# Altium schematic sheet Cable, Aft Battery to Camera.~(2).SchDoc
size Tabloid; Organization: Monterey Bay Aquarium Research Institute; Address1: 7700 Sandholdt Rd; Address2: Moss Landing, CA 95039-9644; Author: Hans Thomas; CompanyName: MBARI; DrawnBy: Hans Thomas; Engineer: Hans Thomas
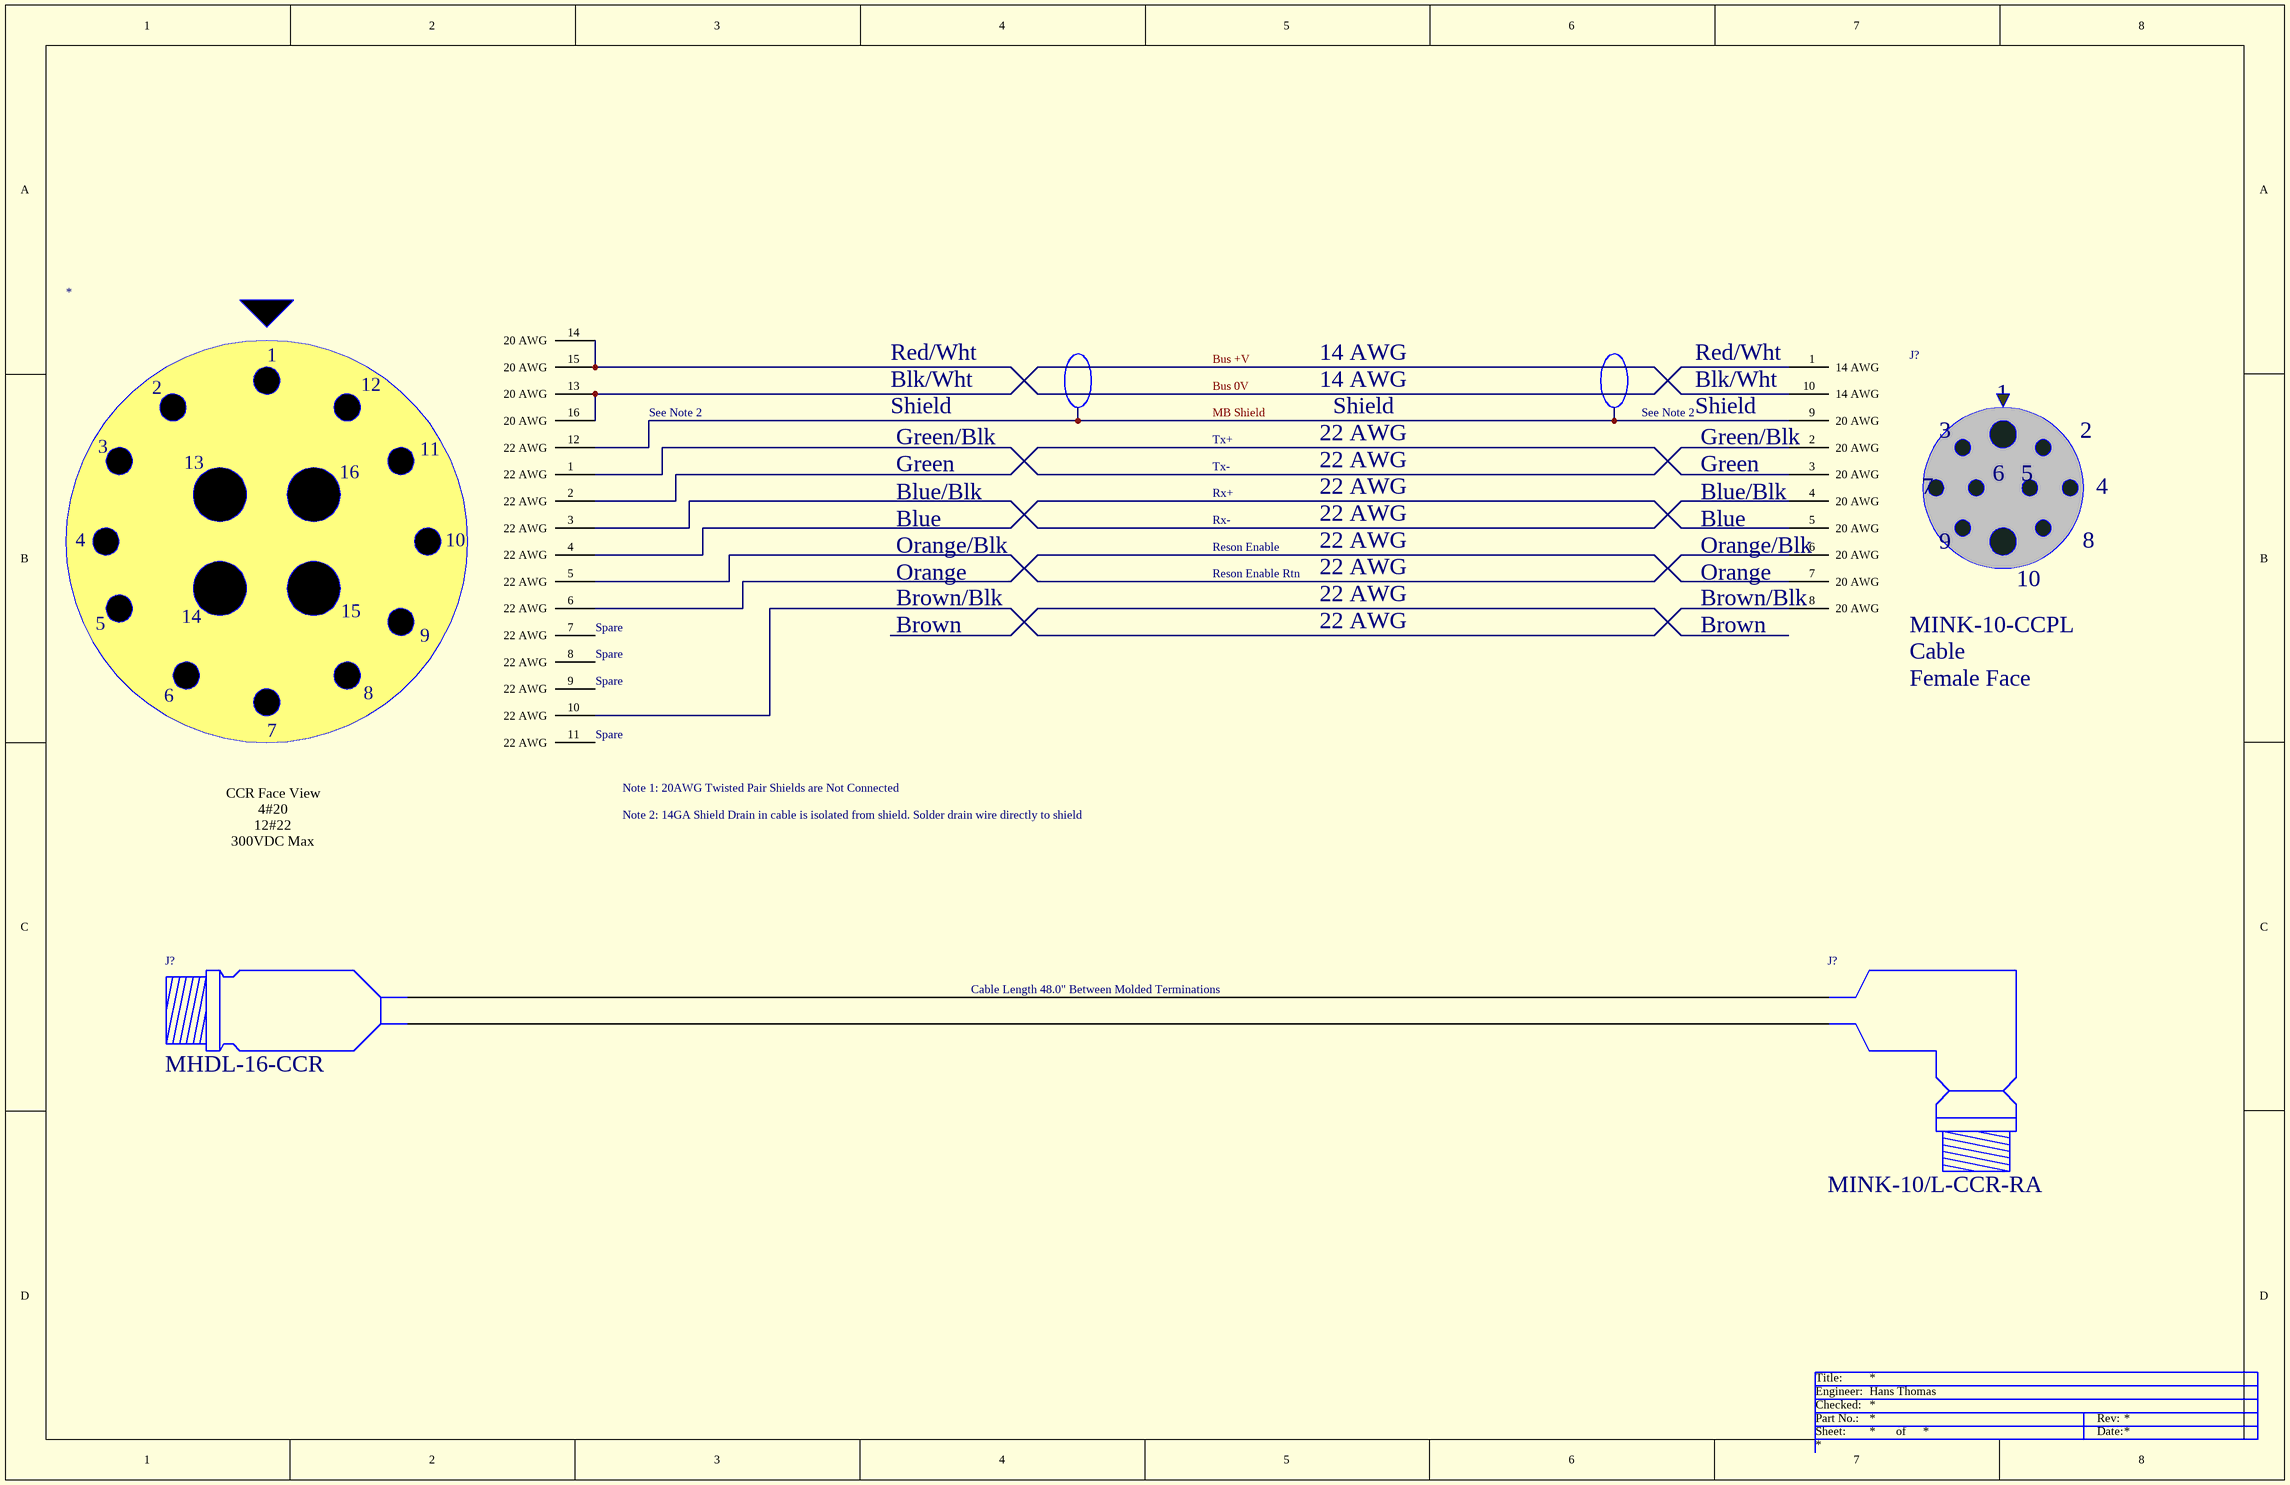
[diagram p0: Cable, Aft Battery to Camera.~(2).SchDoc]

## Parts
(Parts that share a designator on the sheet are numbered #1, #2 ... from top to bottom, then left to right.)
*  MHDL-16-CCR-SOLDER  (value not drawn)
J?#1  MINK-10-CCPL  DescSheet: Cable  View: Female Face
J?#2  MHDL-16-CCR
J?#3  MINK-10/L-CCR-RA

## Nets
Bus 0V: *.14(20_AWG) *.15(20_AWG) J?#1.1(14_AWG)
Bus +V: *.13(20_AWG) *.16(20_AWG) J?#1.10(14_AWG)
MB Shield: *.12(22_AWG) J?#1.9(20_AWG)
Net*_1: *.1(22_AWG) J?#1.2(20_AWG)
Net*_2: *.2(22_AWG) J?#1.3(20_AWG)
Net*_3: *.3(22_AWG) J?#1.4(20_AWG)
Net*_4: *.4(22_AWG) J?#1.5(20_AWG)
Net*_5: *.5(22_AWG) J?#1.6(20_AWG)
Net*_6: *.6(22_AWG) J?#1.7(20_AWG)
Net*_10: *.10(22_AWG) J?#1.8(20_AWG)

Not connected (* = marked no-connect by the designer): * 7(22_AWG) 8(22_AWG) 9(22_AWG) 11(22_AWG)

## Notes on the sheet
- Red/Wht
- 14 AWG
- (near J?#1) Red/Wht
- See Note 2
- Blk/Wht
- Shield
- (near J?#1) Blk/Wht
- Green
- Blue/Blk
- Green/Blk
- Tx+
- Tx-
- Rx+
- 22 AWG
- (near J?#1) Blue/Blk
- (near J?#1) Green/Blk
- Blue
- Orange/Blk
- Rx-
- Reson Enable
- (near J?#1) Orange/Blk
- (near *) Spare
- Brown/Blk
- Orange
- Brown
- Reson Enable Rtn
- (near J?#1) Brown/Blk
- Note 1: 20AWG Twisted Pair Shields are Not Connected
- Note 2: 14GA Shield Drain in cable is isolated from shield. Solder drain wire directly to shield
- Cable Length 48.0" Between Molded Terminations

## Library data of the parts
J?#1 = SEACON-MINK-10-CCP-SOC: Seacon MINK-10/L-CCP Connector
J?#2 = CONN-MIN-CCR-LARGE: Seacon MIN Connector CCR
J?#3 = CONN-MIN-CCR-RA-LARGE: Seacon MIN Connector CCR Right Angle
